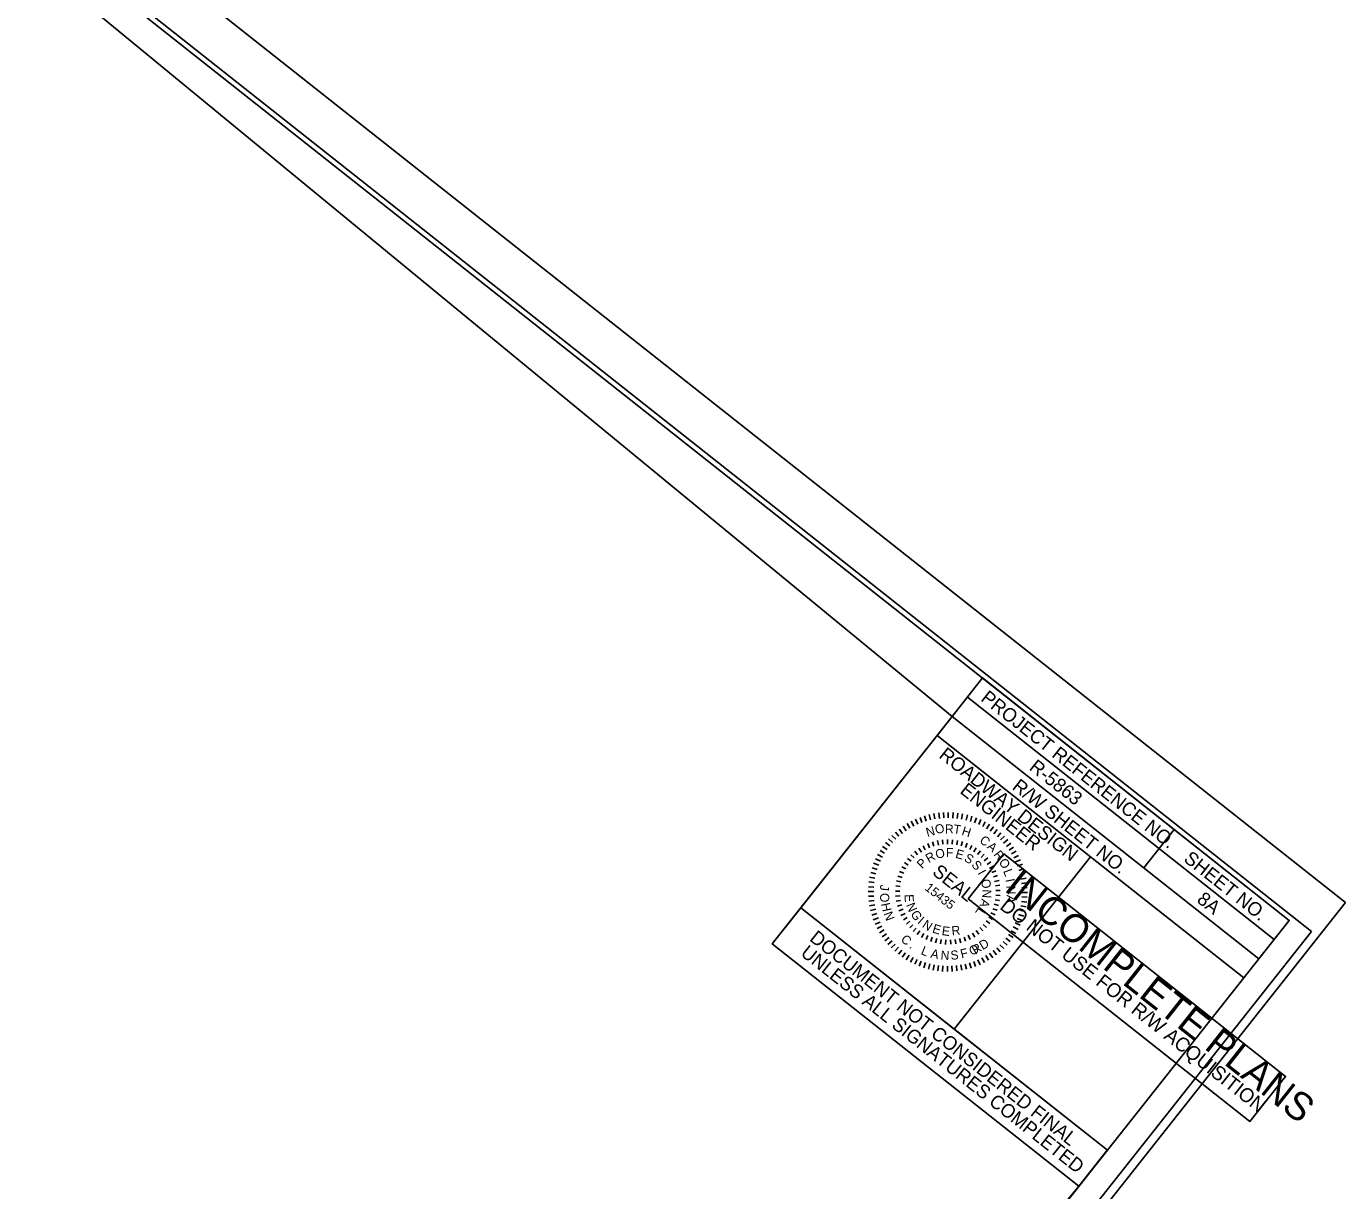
# Model space of a CAD drawing. Extents: x 557005 to 559009, y 505746 to 507841.
# Drawn here: x 558334 to 559009, y 506649 to 507245 of the extents above; entities that cross this region are included whole.
import ezdxf

# ---------------------------------------------------------------- set-up
doc = ezdxf.new("R2010")
doc.units = 0
for name, color, linetype in [('Old_Level_21', 7, 'Continuous'), ('Prop Horizontal Alignment Direction Label', 7, 'Continuous'), ('Prop SS Cut Line', 7, 'Continuous'), ('Prop SS Fill Line', 7, 'Continuous'), ('Prop SS Transition Line', 7, 'Continuous'), ('Scratch_Level_5', 7, 'Continuous'), ('Scratch_Level_9', 7, 'Continuous'), ('Sheet Sticker Exception Certification CELL', 7, 'Continuous'), ('Sheet Sticker Incomplete CELL', 7, 'Continuous')]:
    doc.layers.add(name, color=color, linetype=linetype)

msp = doc.modelspace()

# ---------------------------------------------------------------- linework, layer by layer
at = {"layer": 'Old_Level_21'}
for p, q in [((558784.14, 506836.64), (558785.57, 506834.25)), ((558786.3, 506837.83), (558787.57, 506835.37)), ((558788.51, 506838.9), (558789.64, 506836.36)), ((558790.79, 506839.83), (558791.76, 506837.22)), ((558793.12, 506840.61), (558793.93, 506837.96)), ((558795.49, 506841.26), (558796.14, 506838.56)), ((558797.9, 506841.76), (558798.39, 506839.03)), ((558800.34, 506842.12), (558800.65, 506839.36)), ((558802.78, 506842.33), (558802.94, 506839.56)), ((558805.25, 506842.39), (558805.23, 506839.61)), ((558807.7, 506842.3), (558807.52, 506839.53)), ((558810.15, 506842.06), (558809.8, 506839.31)), ((558812.58, 506841.68), (558812.06, 506838.95)), ((558814.98, 506841.14), (558814.3, 506838.46)), ((558817.35, 506840.47), (558816.51, 506837.82)), ((558819.67, 506839.66), (558818.67, 506837.07)), ((558821.94, 506838.7), (558820.78, 506836.18)), ((558824.14, 506837.61), (558822.84, 506835.16)), ((558826.27, 506836.39), (558824.82, 506834.03)), ((558776.38, 506830.63), (558778.33, 506828.66)), ((558778.18, 506832.3), (558780.01, 506830.22)), ((558780.08, 506833.87), (558781.78, 506831.68)), ((558782.07, 506835.32), (558783.64, 506833.02)), ((558828.33, 506835.04), (558826.74, 506832.77)), ((558830.31, 506833.57), (558828.58, 506831.4)), ((558832.19, 506831.99), (558830.34, 506829.92)), ((558833.97, 506830.29), (558832, 506828.34)), ((558770.29, 506822.94), (558772.65, 506821.49)), ((558771.63, 506824.99), (558773.9, 506823.4)), ((558773.1, 506826.97), (558775.28, 506825.24)), ((558774.69, 506828.85), (558776.75, 506827)), ((558790.16, 506824.02), (558791.44, 506822.1)), ((558792.39, 506825.35), (558793.47, 506823.31)), ((558794.73, 506826.46), (558795.61, 506824.32)), ((558797.17, 506827.34), (558797.84, 506825.12)), ((558799.69, 506827.97), (558800.14, 506825.71)), ((558802.25, 506828.36), (558802.49, 506826.06)), ((558804.84, 506828.51), (558804.85, 506826.19)), ((558807.43, 506828.4), (558807.22, 506826.09)), ((558810, 506828.04), (558809.57, 506825.77)), ((558812.52, 506827.43), (558811.87, 506825.21)), ((558814.97, 506826.59), (558814.11, 506824.44)), ((558817.33, 506825.51), (558816.27, 506823.45)), ((558819.57, 506824.21), (558818.32, 506822.27)), ((558835.64, 506828.49), (558833.56, 506826.66)), ((558837.21, 506826.59), (558835.01, 506824.89)), ((558838.66, 506824.6), (558836.36, 506823.03)), ((558767.02, 506816.33), (558769.61, 506815.33)), ((558767.97, 506818.6), (558770.49, 506817.44)), ((558769.06, 506820.8), (558771.51, 506819.5)), ((558782.82, 506816.78), (558784.73, 506815.47)), ((558784.39, 506818.85), (558786.16, 506817.37)), ((558786.14, 506820.75), (558787.77, 506819.11)), ((558788.07, 506822.49), (558789.53, 506820.69)), ((558821.68, 506822.7), (558820.24, 506820.88)), ((558820.24, 506820.88), (558821.68, 506822.7)), ((558823.63, 506820.99), (558822.03, 506819.32)), ((558825.41, 506819.1), (558823.65, 506817.6)), ((558827, 506817.05), (558825.1, 506815.72)), ((558839.98, 506822.53), (558837.59, 506821.11)), ((558841.17, 506820.38), (558838.71, 506819.1)), ((558842.24, 506818.16), (558839.7, 506817.04)), ((558765.53, 506811.64), (558768.22, 506810.96)), ((558766.2, 506814.01), (558768.85, 506813.17)), ((558779.43, 506809.8), (558781.63, 506809.1)), ((558780.33, 506812.23), (558782.46, 506811.32)), ((558781.47, 506814.56), (558783.5, 506813.45)), ((558828.38, 506814.86), (558826.37, 506813.72)), ((558829.54, 506812.54), (558827.43, 506811.6)), ((558830.48, 506810.12), (558828.28, 506809.39)), ((558843.16, 506815.88), (558840.56, 506814.92)), ((558843.95, 506813.55), (558841.3, 506812.74)), ((558844.6, 506811.18), (558841.9, 506810.53)), ((558764.38, 506804.36), (558767.14, 506804.18)), ((558764.61, 506806.81), (558767.37, 506806.46)), ((558765, 506809.24), (558767.73, 506808.73)), ((558778.35, 506804.74), (558780.64, 506804.47)), ((558778.77, 506807.3), (558781.03, 506806.81)), ((558831.18, 506807.62), (558828.92, 506807.11)), ((558831.63, 506805.07), (558829.33, 506804.77)), ((558845.1, 506808.77), (558842.37, 506808.29)), ((558845.45, 506806.34), (558842.7, 506806.02)), ((558845.66, 506803.89), (558842.89, 506803.74)), ((558764.29, 506801.91), (558767.06, 506801.89)), ((558764.35, 506799.45), (558767.12, 506799.6)), ((558764.56, 506797), (558767.31, 506797.32)), ((558778.17, 506802.15), (558780.49, 506802.11)), ((558778.25, 506799.56), (558780.56, 506799.74)), ((558778.58, 506796.99), (558780.86, 506797.39)), ((558831.49, 506797.32), (558829.2, 506797.69)), ((558831.79, 506799.89), (558829.48, 506800.04)), ((558831.83, 506802.48), (558829.52, 506802.41)), ((558845.4, 506796.52), (558842.65, 506796.87)), ((558845.64, 506798.97), (558842.87, 506799.15)), ((558845.72, 506801.43), (558842.95, 506801.45)), ((558764.91, 506794.56), (558767.64, 506795.05)), ((558765.42, 506792.15), (558768.11, 506792.8)), ((558766.06, 506789.78), (558768.71, 506790.59)), ((558779.16, 506794.46), (558781.38, 506795.08)), ((558779.97, 506792), (558782.13, 506792.83)), ((558781.03, 506789.63), (558783.09, 506790.66)), ((558829.14, 506789.92), (558827.06, 506790.94)), ((558830.16, 506792.31), (558827.99, 506793.12)), ((558830.94, 506794.78), (558828.71, 506795.37)), ((558843.81, 506789.32), (558841.16, 506790.17)), ((558844.48, 506791.69), (558841.79, 506792.37)), ((558845.02, 506794.09), (558842.29, 506794.61)), ((558766.85, 506787.45), (558769.45, 506788.42)), ((558767.78, 506785.17), (558770.32, 506786.3)), ((558768.84, 506782.96), (558771.3, 506784.23)), ((558782.3, 506787.36), (558784.26, 506788.6)), ((558785.6, 506786.67), (558783.77, 506785.25)), ((558785.47, 506783.27), (558787.15, 506784.86)), ((558787.33, 506781.47), (558788.86, 506783.21)), ((558821.44, 506783.47), (558822.99, 506781.75)), ((558824.77, 506783.51), (558823.07, 506785.08)), ((558826.43, 506785.51), (558824.58, 506786.9)), ((558827.89, 506787.65), (558825.92, 506788.86)), ((558840.95, 506782.53), (558838.5, 506783.84)), ((558842.04, 506784.74), (558839.52, 506785.89)), ((558843, 506787.01), (558840.4, 506788.01)), ((558770.04, 506780.81), (558772.42, 506782.23)), ((558771.36, 506778.73), (558773.65, 506780.3)), ((558772.81, 506776.74), (558775, 506778.44)), ((558774.37, 506774.84), (558776.46, 506776.67)), ((558789.37, 506779.86), (558790.72, 506781.74)), ((558791.54, 506778.45), (558792.7, 506780.45)), ((558793.85, 506777.26), (558794.81, 506779.37)), ((558796.25, 506776.3), (558797.01, 506778.49)), ((558798.75, 506775.57), (558799.29, 506777.82)), ((558801.3, 506775.09), (558801.61, 506777.38)), ((558803.88, 506774.86), (558803.97, 506777.17)), ((558806.47, 506774.87), (558806.34, 506777.18)), ((558809.05, 506775.14), (558808.7, 506777.42)), ((558811.59, 506775.65), (558811.02, 506777.89)), ((558814.07, 506776.41), (558813.29, 506778.58)), ((558816.46, 506777.4), (558815.48, 506779.49)), ((558818.75, 506778.62), (558817.57, 506780.6)), ((558820.91, 506780.05), (558819.54, 506781.91)), ((558835.32, 506774.49), (558833.26, 506776.34)), ((558836.91, 506776.37), (558834.74, 506778.09)), ((558838.38, 506778.34), (558836.11, 506779.93)), ((558839.73, 506780.4), (558837.36, 506781.85)), ((558776.05, 506773.05), (558778.02, 506775)), ((558777.83, 506771.35), (558779.68, 506773.42)), ((558779.71, 506769.76), (558781.43, 506771.94)), ((558781.68, 506768.29), (558783.27, 506770.57)), ((558783.74, 506766.95), (558785.19, 506769.31)), ((558825.87, 506766.7), (558824.45, 506769.08)), ((558827.94, 506768.02), (558826.37, 506770.31)), ((558829.93, 506769.47), (558828.23, 506771.66)), ((558831.83, 506771.03), (558830, 506773.12)), ((558833.63, 506772.71), (558831.68, 506774.68)), ((558785.87, 506765.72), (558787.18, 506768.17)), ((558788.07, 506764.64), (558789.23, 506767.16)), ((558790.34, 506763.68), (558791.35, 506766.27)), ((558792.66, 506762.86), (558793.5, 506765.51)), ((558795.03, 506762.19), (558795.71, 506764.88)), ((558797.43, 506761.66), (558797.95, 506764.39)), ((558799.86, 506761.27), (558800.21, 506764.03)), ((558802.31, 506761.04), (558802.49, 506763.81)), ((558804.76, 506760.95), (558804.78, 506763.72)), ((558807.23, 506761.01), (558807.07, 506763.78)), ((558809.68, 506761.22), (558809.36, 506763.97)), ((558812.11, 506761.57), (558811.63, 506764.31)), ((558814.52, 506762.08), (558813.87, 506764.77)), ((558816.89, 506762.72), (558816.08, 506765.38)), ((558819.22, 506763.51), (558818.25, 506766.11)), ((558821.5, 506764.44), (558820.37, 506766.98)), ((558823.72, 506765.51), (558822.44, 506767.97))]:
    msp.add_line(p, q, dxfattribs=at)
at = {"layer": 'Prop Horizontal Alignment Direction Label'}
msp.add_lwpolyline([(559008.53, 506796.2), (557687.57, 507840.68), (557005.31, 506977.82), (558326.27, 505933.34)], close=True, dxfattribs=at)
at = {"layer": 'Prop SS Cut Line'}
for p, q in [((558814.98, 506901.37), (558971.9, 506777.29)), ((558807.23, 506891.56), (558799.47, 506881.76)), ((558807.23, 506891.56), (558964.15, 506767.48)), ((558807.23, 506891.56), (558964.15, 506767.48)), ((558920.82, 506833.61), (558905.32, 506814)), ((558877.95, 506819.7), (558808.21, 506731.49))]:
    msp.add_line(p, q, dxfattribs=at)
for points in [[(558979.69, 506787.13), (557803.06, 507717.49), (557151.81, 506893.85), (558328.44, 505963.5)], [(558822.76, 506911.21), (558979.69, 506787.13), (558964.15, 506767.48), (558807.23, 506891.56)], [(558799.47, 506881.76), (558877.95, 506819.7), (558808.18, 506731.46), (558729.7, 506793.51)], [(558877.95, 506819.7), (558956.4, 506757.68), (558886.62, 506669.43), (558808.18, 506731.46)]]:
    msp.add_lwpolyline(points, close=True, dxfattribs=at)
at = {"layer": 'Prop SS Fill Line'}
msp.add_lwpolyline([(558991.07, 506781.38), (557683.84, 507815), (557029.43, 506987.37), (558336.66, 505953.74)], close=True, dxfattribs=at)
at = {"layer": 'Scratch_Level_5'}
for points in [[(558502.21, 506199.86), (558069.07, 506542.35), (558000.13, 506451.2), (557930.66, 506511.32), (557889.73, 506539.36), (557425.46, 506933.59), (557395.12, 506959.79), (557368.13, 506966.2), (557439.22, 507142.63), (557392.13, 507195.25), (557803.85, 507716.87), (558807.23, 506891.56), (558715.12, 506775.08), (558872.03, 506651.01)], [(558502.21, 506199.86), (558069.07, 506542.35), (558000.13, 506451.2), (557930.66, 506511.32), (557889.73, 506539.36), (557425.46, 506933.59), (557395.12, 506959.79), (557474.03, 506970.73), (557439.22, 507142.63), (557392.13, 507195.25), (557803.85, 507716.87), (558807.23, 506891.56), (558715.12, 506775.08), (558872.03, 506651.01)]]:
    msp.add_lwpolyline(points, close=True, dxfattribs=at)
at = {"layer": 'Scratch_Level_9'}
msp.add_line((559008.53, 506796.2), (557687.57, 507840.68), dxfattribs=at)
at = {"layer": 'Sheet Sticker Exception Certification CELL'}
for p, q in [((558715.12, 506775.08), (558729.7, 506793.51)), ((558729.7, 506793.51), (558886.61, 506669.44)), ((558872.03, 506651.01), (558715.12, 506775.08)), ((558886.6, 506669.43), (558872.03, 506651))]:
    msp.add_line(p, q, dxfattribs=at)
at = {"layer": 'Sheet Sticker Incomplete CELL'}
msp.add_lwpolyline([(558815.43, 506798.18), (558833.65, 506821.22), (558977.78, 506707.25), (558959.56, 506684.21)], close=True, dxfattribs=at)

# ---------------------------------------------------------------- texts
at = {"layer": 'Old_Level_21'}
for s, height, rotation, p in [('O', 4.62, 13.30413, (558799, 506831.24)), ('N', 4.62, 15.26356, (558794.5, 506829.83)), ('R', 4.62, 0.24739, (558803.56, 506831.59)), ('T', 4.62, 352.08643, (558807.6, 506831.69)), ('H', 4.62, 342.65448, (558811.77, 506830.96)), ('C', 4.62, 318.94379, (558820.82, 506827.57)), ('O', 4.62, 15.12369, (558799.3, 506818.5)), ('F', 4.62, 359.82744, (558804.03, 506819.51)), ('E', 4.62, 344.5312, (558808.55, 506819.26)), ('A', 4.62, 318.94379, (558824.72, 506824.36)), ('R', 4.62, 306.93449, (558828.14, 506820.78)), ('P', 4.62, 45.71618, (558791.9, 506813.23)), ('R', 4.62, 30.41993, (558795.29, 506816.38)), ('S', 4.62, 329.23495, (558812.94, 506817.81)), ('S', 4.62, 313.93871, (558816.79, 506815.24)), ('O', 4.62, 303.87767, (558830.82, 506816.95)), ('SEAL', 6.938, 321.58683, (558796.56, 506811.02)), ('I', 4.62, 298.64246, (558820.02, 506811.41)), ('L', 4.62, 290.74139, (558833.23, 506812.42)), ('J', 4.62, 265.52184, (558770.46, 506805.51)), ('15435', 4.622, 321.58683, (558792.9, 506803.07)), ('O', 4.62, 283.34621, (558821.83, 506807.68)), ('N', 4.62, 268.04997, (558822.69, 506803.04)), ('I', 4.62, 281.16592, (558834.48, 506808)), ('N', 4.62, 271.87146, (558834.94, 506804.85)), ('O', 4.62, 273.59366, (558770.24, 506800.98)), ('H', 4.62, 282.23641, (558770.77, 506795.59)), ('E', 4.62, 271.65692, (558782.9, 506800.46)), ('N', 4.62, 292.51199, (558783.55, 506795.03)), ('A', 4.62, 252.75372, (558822.33, 506798.5)), ('A', 4.62, 262.10393, (558835.21, 506800.29)), ('N', 4.62, 290.90899, (558772.04, 506790.6)), ('G', 4.62, 301.27823, (558785.75, 506790.52)), ('I', 4.62, 319.37302, (558789.14, 506785.94)), ('L', 4.62, 237.45748, (558820.66, 506793.99)), ('N', 4.62, 327.00268, (558791.51, 506783.87)), ('E', 4.62, 342.39475, (558796.73, 506781.04)), ('E', 4.62, 352.38063, (558801.68, 506779.64)), ('R', 4.62, 6.15172, (558807.13, 506779.43)), ('C', 4.62, 317.67678, (558780.56, 506776.94)), (' RD', 4.622, 31.25925, (558817.51, 506768.62)), ('.', 4.62, 325.41913, (558784.99, 506773.27)), ('L', 4.62, 338.20345, (558790.89, 506769.9)), ('A', 4.62, 347.20601, (558795.86, 506768.12)), ('N', 4.62, 356.02863, (558801.18, 506767.11)), ('S', 4.62, 4.91126, (558806.57, 506766.93)), ('F', 4.62, 13.79388, (558812.02, 506767.62)), ('O ', 4.622, 22.5865, (558816.97, 506769.02))]:
    msp.add_text(s, height=height, rotation=rotation, dxfattribs=at).set_placement(p)
at = {"layer": 'Prop SS Cut Line'}
for s, p in [('PROJECT REFERENCE NO.', (558821.41, 506899.92)), ('ROADWAY DESIGN', (558799.97, 506870.78)), ('ENGINEER', (558810.72, 506852.65)), ('R/W SHEET NO.', (558837.44, 506854.67)), ('SHEET NO.', (558925.21, 506817.72))]:
    msp.add_text(s, height=7, rotation=321.66667, dxfattribs=at).set_placement(p)
at = {"layer": 'Prop SS Transition Line'}
for s, p in [('R-5863', (558846.17, 506864.59)), ('8A', (558931.96, 506796.83))]:
    msp.add_text(s, height=7, rotation=321.66667, dxfattribs=at).set_placement(p)
at = {"layer": 'Sheet Sticker Exception Certification CELL'}
for s, p in [('DOCUMENT NOT CONSIDERED FINAL', (558733.79, 506777.09)), ('UNLESS ALL SIGNATURES COMPLETED', (558729.21, 506769.49))]:
    msp.add_text(s, height=7, rotation=321.66667, dxfattribs=at).set_placement(p)
at = {"layer": 'Sheet Sticker Incomplete CELL'}
for s, height, p in [('INCOMPLETE PLANS', 14.4, (558833.3, 506802.71)), ('DO NOT USE FOR R/W ACQUISITION', 7.2, (558831.09, 506793.38))]:
    msp.add_text(s, height=height, rotation=321.66667, dxfattribs=at).set_placement(p)

doc.saveas('drawing.dxf')
